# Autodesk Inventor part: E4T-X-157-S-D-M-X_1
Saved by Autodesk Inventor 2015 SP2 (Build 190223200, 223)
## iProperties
Created: 2016-05
Part Number: E4T-X-157-S-D-M-X_1
Material: Allgemein
Document SubType Name: Modeling
Designer: ryll
Density: 1 g/cm^3
Appearance: Vorgabe
Author: ryll
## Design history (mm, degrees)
node "E4T-X-157-S-D-M-X_11"
node "E4T-X-157-S-D-M-X_1"
node "Basis1"
